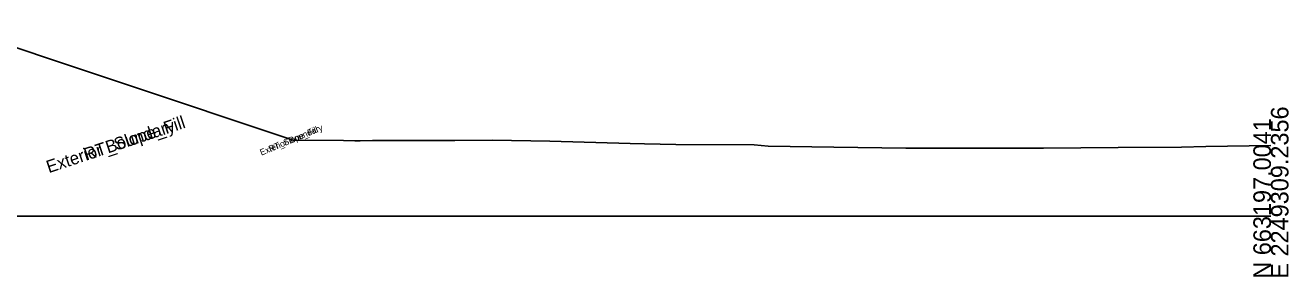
# Model space of a CAD drawing. Extents: x -26 to 2603, y -10 to 9566.
# Drawn here: x 1401.4 to 1602.8, y 6490.3 to 6530.4 of the extents above; entities that cross this region are included whole.
import ezdxf

# ---------------------------------------------------------------- set-up
doc = ezdxf.new("R2010")
doc.units = 0
for name, color, linetype in [('Exist Cross Section Cell', 7, 'Continuous'), ('Exist XS Ground Line', 7, 'Continuous'), ('Scratch_Level_9', 7, 'Continuous')]:
    doc.layers.add(name, color=color, linetype=linetype)

msp = doc.modelspace()

# ---------------------------------------------------------------- linework, layer by layer
at = {"layer": 'Exist Cross Section Cell'}
msp.add_line((1300, 6500), (1600, 6500), dxfattribs=at)
at = {"layer": 'Exist XS Ground Line'}
for p, q in [((1444.1, 6512.12), (1452.17, 6512.03)), ((1452.17, 6512.03), (1453.93, 6512.02)), ((1453.93, 6512.02), (1454.82, 6512)), ((1454.82, 6512), (1456.77, 6512.03)), ((1456.77, 6512.03), (1469.92, 6512.06)), ((1469.92, 6512.06), (1475.89, 6512.12)), ((1475.89, 6512.12), (1485.03, 6511.92)), ((1485.03, 6511.92), (1497.86, 6511.55)), ((1497.86, 6511.55), (1500.13, 6511.49)), ((1500.13, 6511.49), (1505.13, 6511.4)), ((1505.13, 6511.4), (1517.63, 6511.33)), ((1517.63, 6511.33), (1519.83, 6511.14)), ((1519.83, 6511.14), (1530.34, 6511)), ((1530.34, 6511), (1541.79, 6510.85)), ((1541.79, 6510.85), (1545.45, 6510.83)), ((1545.45, 6510.83), (1553.49, 6510.8)), ((1553.49, 6510.8), (1560.55, 6510.83)), ((1560.55, 6510.83), (1563.76, 6510.82)), ((1563.76, 6510.82), (1575.66, 6510.95)), ((1575.66, 6510.95), (1585.73, 6511)), ((1585.73, 6511), (1589.62, 6511.11)), ((1589.62, 6511.11), (1600, 6511.27))]:
    msp.add_line(p, q, dxfattribs=at)
msp.add_lwpolyline([(1389.16, 6530.44), (1444.1, 6512.12)], dxfattribs=at)

# ---------------------------------------------------------------- texts
at = {"layer": 'Exist Cross Section Cell'}
for s, p in [('E 2249309.2356', (1602.8, 6490)), ('N 663197.0041', (1600, 6490))]:
    msp.add_text(s, height=2.8, rotation=90, dxfattribs=at).set_placement(p)
at = {"layer": 'Scratch_Level_9'}
for s, height, rotation, p in [('Exterior Boundary', 2, 18.4332, (1405.16, 6506.82)), ('Exterior Boundary', 2, 18.4332, (1405.16, 6506.82)), ('RT_Slope_Fill', 2, 18.4332, (1411.16, 6508.82)), ('RT_Slope_Fill', 2, 18.4332, (1411.16, 6508.82)), ('Exterior Boundary', 1, 22.5575, (1439.06, 6509.62)), ('Exterior Boundary', 1, 22.5575, (1439.06, 6509.62)), ('RT_Slope_Fill', 1, 22.5575, (1440.46, 6510.2)), ('RT_Slope_Fill', 1, 22.5575, (1440.46, 6510.2))]:
    msp.add_text(s, height=height, rotation=rotation, dxfattribs=at).set_placement(p)

doc.saveas('drawing.dxf')
